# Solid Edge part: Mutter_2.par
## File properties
Dokumentum tartalom típus: 0
Last saved by: ahadarics
Revision: 76
Sűrűség: 0,000 kg/m^3
Pontosság: 0,990
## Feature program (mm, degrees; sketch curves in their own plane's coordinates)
base feature "unnamed BaseFeature 1"
thread "unnamed Thread 1"
chamfer "unnamed Chamfer 1"
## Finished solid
Body 1: solid body, 23 faces, 46 edges, 24 vertices.
  Faces by surface: cone 14, plane 8, cylinder 1
  Edges by curve: spline 24, circle 16, line 6
Bounding box of the edges (mm): 4.000 x 8.083 x 7.000, from (0, -4.0415, -3.5) to (4, 4.0415, 3.5).
Cylindrical faces by radius (mm): R1.621 x1
Conical faces (half-angle, radius in mm at the cone's reference point): 45 deg R1.621 x1, 45 deg R1.821 x1, 60 deg R3.7707 x12
Planar faces by outward normal: +x 1, +z 1, -x 1, -z 1, oblique 4
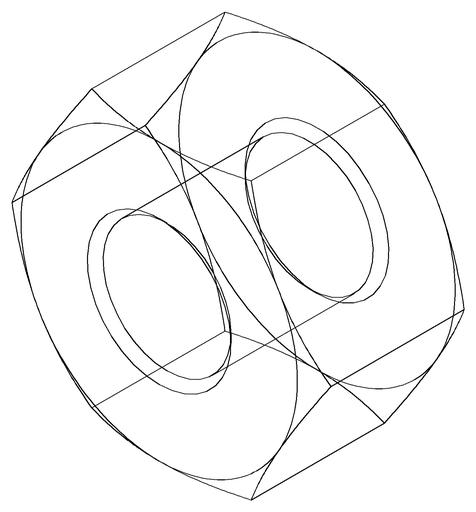
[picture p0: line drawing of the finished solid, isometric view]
